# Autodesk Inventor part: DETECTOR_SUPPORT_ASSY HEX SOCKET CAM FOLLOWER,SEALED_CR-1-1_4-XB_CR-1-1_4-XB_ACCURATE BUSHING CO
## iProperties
Shininess: 64.0
Length Units: 11272
Angle Units: 11279
Time Units: 11290
Mass Units: 11286
Length Display Precision: 3
Angle Display Precision: 2
Compacted: True
Part Number: DETECTOR_SUPPORT_ASSY HEX SOCKET CAM FOLLOWER,SEALED_CR-1-1_4-XB_CR-1-1_4-XB_ACCURATE BUSHING CO
Document SubType Name: Modeling
Created: 2004-08
Designer: John Blackburn
Material: MILD_STEEL
Manufacturer: Standard
Standards Organization: Custom
Density: 0.0
Volumn: 0.0
Area: 0.0
PropertySet Name: Model Information
Control State: 0
Master: False
Checked Out: False
Author: John Blackburn
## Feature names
1. Base1
